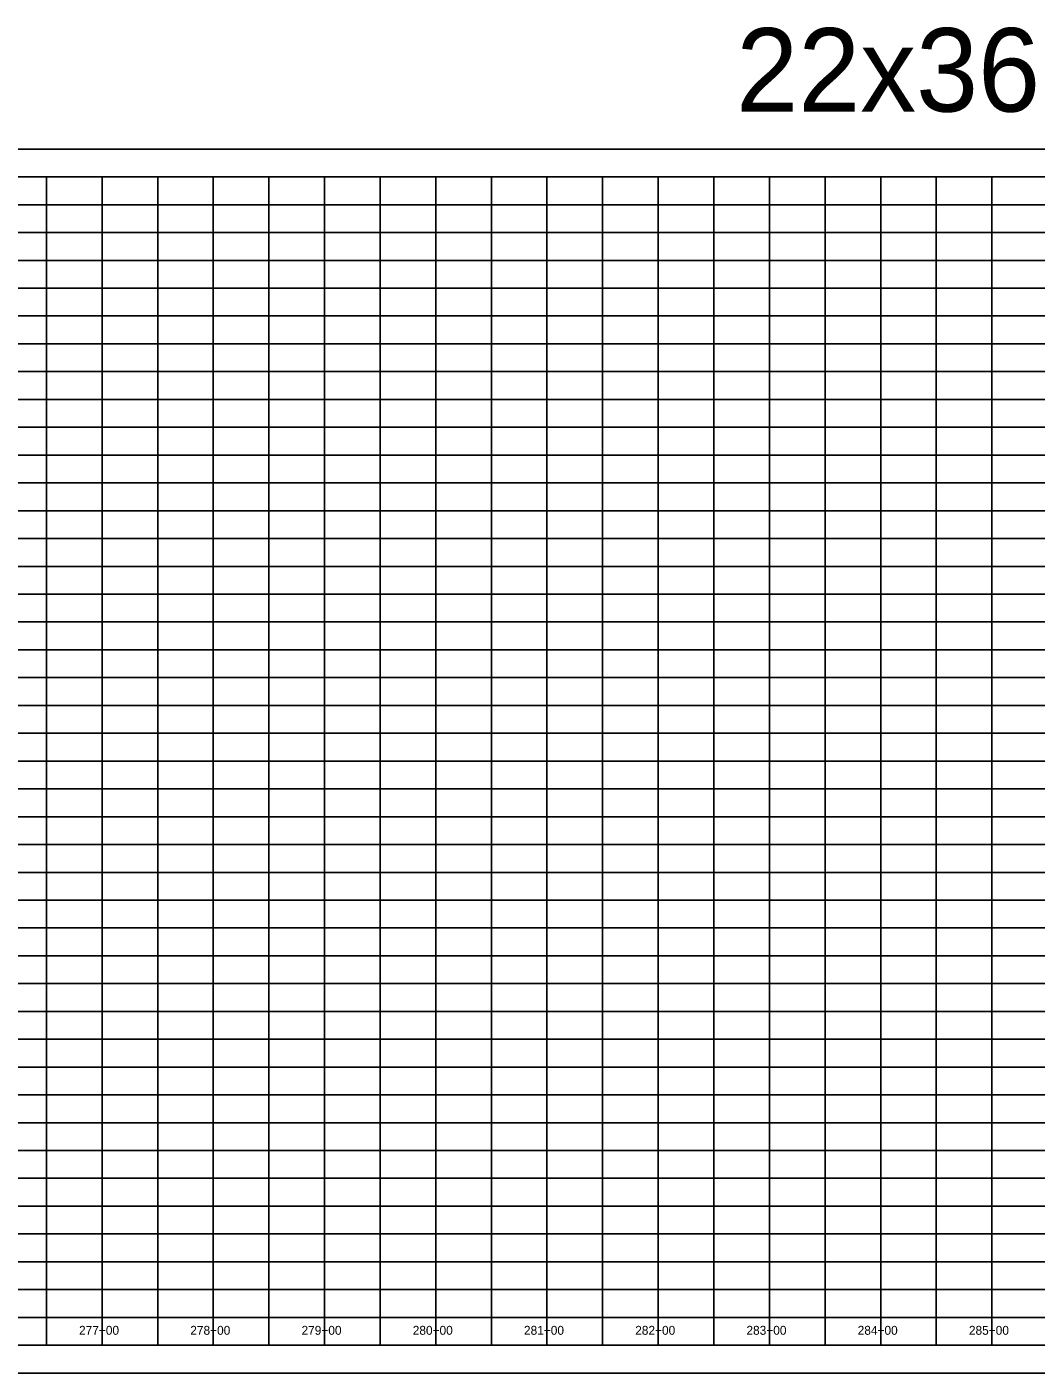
# Model space of a CAD drawing. Extents: x 1873632 to 1926512, y 813126 to 836257.
# Drawn here: x 1905995 to 1906903, y 827963 to 829173 of the extents above; entities that cross this region are included whole.
import ezdxf

# ---------------------------------------------------------------- set-up
doc = ezdxf.new("R2010")
doc.units = 0
for name, color, linetype in [('RD_DDB_StaTX', 7, 'Continuous'), ('RD_PD_WallFill', 7, 'Continuous'), ('RD_SHT_IplotShp', 7, 'Continuous')]:
    doc.layers.add(name, color=color, linetype=linetype)

msp = doc.modelspace()

# ---------------------------------------------------------------- linework, layer by layer
at = {"layer": 'RD_PD_WallFill'}
for p, q in [((1905062.9, 829038.1), (1910412.9, 829038.1)), ((1905062.9, 829038.1), (1906812.9, 829038.1)), ((1906012.9, 827988.1), (1906012.9, 829038.1)), ((1906012.9, 827988.1), (1906012.9, 829038.1)), ((1906062.9, 827988.1), (1906062.9, 829038.1)), ((1906062.9, 827988.1), (1906062.9, 829038.1)), ((1906112.9, 827988.1), (1906112.9, 829038.1)), ((1906112.9, 827988.1), (1906112.9, 829038.1)), ((1906162.9, 827988.1), (1906162.9, 829038.1)), ((1906162.9, 827988.1), (1906162.9, 829038.1)), ((1906212.9, 827988.1), (1906212.9, 829038.1)), ((1906212.9, 827988.1), (1906212.9, 829038.1)), ((1906262.9, 827988.1), (1906262.9, 829038.1)), ((1906262.9, 827988.1), (1906262.9, 829038.1)), ((1906312.9, 827988.1), (1906312.9, 829038.1)), ((1906312.9, 827988.1), (1906312.9, 829038.1)), ((1906362.9, 827988.1), (1906362.9, 829038.1)), ((1906362.9, 827988.1), (1906362.9, 829038.1)), ((1906412.9, 827988.1), (1906412.9, 829038.1)), ((1906412.9, 827988.1), (1906412.9, 829038.1)), ((1906462.9, 827988.1), (1906462.9, 829038.1)), ((1906462.9, 827988.1), (1906462.9, 829038.1)), ((1906512.9, 827988.1), (1906512.9, 829038.1)), ((1906512.9, 827988.1), (1906512.9, 829038.1)), ((1906562.9, 827988.1), (1906562.9, 829038.1)), ((1906562.9, 827988.1), (1906562.9, 829038.1)), ((1906612.9, 827988.1), (1906612.9, 829038.1)), ((1906612.9, 827988.1), (1906612.9, 829038.1)), ((1906662.9, 827988.1), (1906662.9, 829038.1)), ((1906662.9, 827988.1), (1906662.9, 829038.1)), ((1906712.9, 827988.1), (1906712.9, 829038.1)), ((1906712.9, 827988.1), (1906712.9, 829038.1)), ((1906762.9, 827988.1), (1906762.9, 829038.1)), ((1906762.9, 827988.1), (1906762.9, 829038.1)), ((1906812.9, 827988.1), (1906812.9, 829038.1)), ((1906812.9, 827988.1), (1906812.9, 829038.1)), ((1906862.9, 827988.1), (1906862.9, 829038.1)), ((1906862.9, 827988.1), (1906862.9, 829038.1)), ((1905512.9, 829013.1), (1910412.9, 829013.1)), ((1905512.9, 829013.1), (1910412.9, 829013.1)), ((1905512.9, 828988.1), (1910412.9, 828988.1)), ((1905512.9, 828963.1), (1910412.9, 828963.1)), ((1905512.9, 828938.1), (1910412.9, 828938.1)), ((1905512.9, 828913.1), (1910412.9, 828913.1)), ((1905062.9, 828888.1), (1910412.9, 828888.1)), ((1905062.9, 828863.1), (1910412.9, 828863.1)), ((1905062.9, 828838.1), (1910412.9, 828838.1)), ((1905062.9, 828813.1), (1910412.9, 828813.1)), ((1905062.9, 828788.1), (1910412.9, 828788.1)), ((1905062.9, 828763.1), (1910412.9, 828763.1)), ((1905062.9, 828738.1), (1910412.9, 828738.1)), ((1905062.9, 828713.1), (1910412.9, 828713.1)), ((1905062.9, 828688.1), (1910412.9, 828688.1)), ((1905062.9, 828663.1), (1910412.9, 828663.1)), ((1905062.9, 828638.1), (1910412.9, 828638.1)), ((1905062.9, 828613.1), (1910412.9, 828613.1)), ((1905062.9, 828588.1), (1910412.9, 828588.1)), ((1905062.9, 828563.1), (1910412.9, 828563.1)), ((1905062.9, 828538.1), (1910412.9, 828538.1)), ((1905062.9, 828513.1), (1910412.9, 828513.1)), ((1905062.9, 828488.1), (1910412.9, 828488.1)), ((1905062.9, 828463.1), (1910412.9, 828463.1)), ((1905062.9, 828438.1), (1910412.9, 828438.1)), ((1905062.9, 828413.1), (1910412.9, 828413.1)), ((1905062.9, 828388.1), (1910412.9, 828388.1)), ((1905062.9, 828363.1), (1910412.9, 828363.1)), ((1905062.9, 828338.1), (1910412.9, 828338.1)), ((1905062.9, 828313.1), (1910412.9, 828313.1)), ((1905062.9, 828288.1), (1910412.9, 828288.1)), ((1905062.9, 828263.1), (1910412.9, 828263.1)), ((1905062.9, 828238.1), (1910412.9, 828238.1)), ((1905062.9, 828213.1), (1910412.9, 828213.1)), ((1905062.9, 828188.1), (1910412.9, 828188.1)), ((1905062.9, 828163.1), (1910412.9, 828163.1)), ((1905062.9, 828138.1), (1910412.9, 828138.1)), ((1905062.9, 828113.1), (1910412.9, 828113.1)), ((1905062.9, 828088.1), (1910412.9, 828088.1)), ((1905062.9, 828063.1), (1910412.9, 828063.1)), ((1905062.9, 828038.1), (1910412.9, 828038.1)), ((1905062.9, 828013.1), (1910412.9, 828013.1)), ((1905062.9, 827988.1), (1910412.9, 827988.1)), ((1905062.9, 827988.1), (1910412.9, 827988.1))]:
    msp.add_line(p, q, dxfattribs=at)
at = {"layer": 'RD_SHT_IplotShp'}
msp.add_lwpolyline([(1905037.9, 827963.1), (1910437.9, 827963.1), (1910437.9, 829063.1), (1905037.9, 829063.1)], close=True, dxfattribs=at)

# ---------------------------------------------------------------- texts
at = {"layer": 'RD_DDB_StaTX'}
for s, p in [('277+00', (1906042.2, 827997.5)), ('278+00', (1906142.2, 827997.5)), ('279+00', (1906242.2, 827997.5)), ('280+00', (1906342.2, 827997.5)), ('281+00', (1906442.2, 827997.5)), ('282+00', (1906542.2, 827997.5)), ('283+00', (1906642.2, 827997.5)), ('284+00', (1906742.2, 827997.5)), ('285+00', (1906842.2, 827997.5))]:
    msp.add_text(s, height=8, dxfattribs=at).set_placement(p)
at = {"layer": 'RD_PD_WallFill'}
msp.add_text('22x36', height=75, dxfattribs=at).set_placement((1906633, 829096.8))
msp.add_text('22x36', height=75, dxfattribs=at).set_placement((1906633, 829096.8))

doc.saveas('drawing.dxf')
